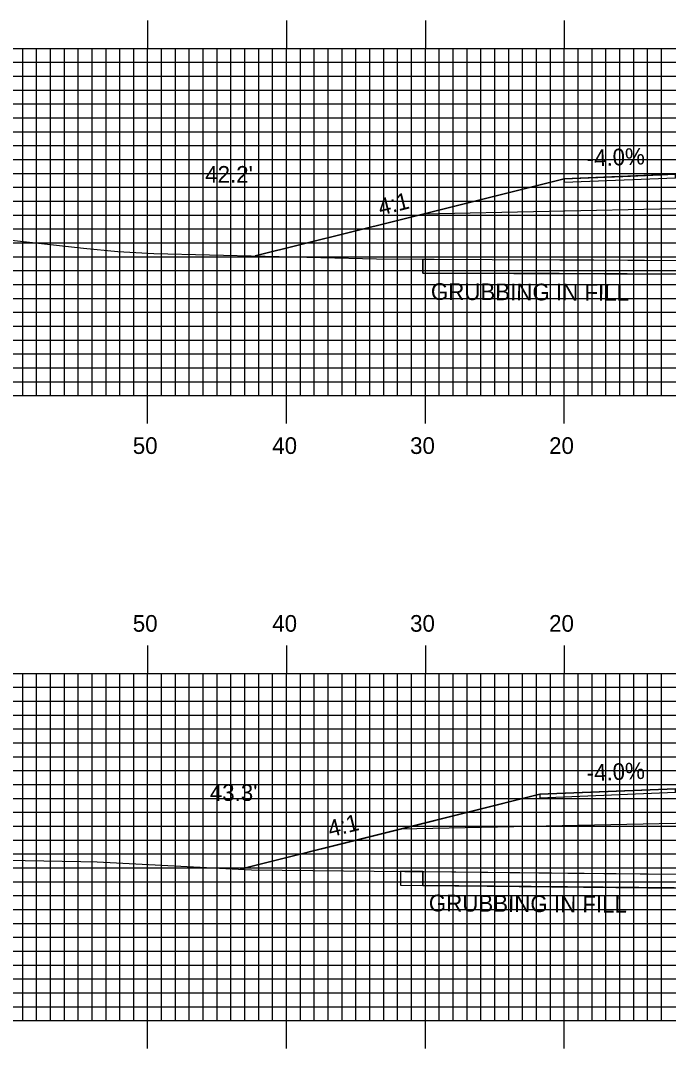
# Model space of a CAD drawing. Extents: x 1773990 to 1774333, y 442591 to 442811.
# Drawn here: x 1774096.5 to 1774143.2, y 442686.7 to 442760.7 of the extents above; entities that cross this region are included whole.
import ezdxf

# ---------------------------------------------------------------- set-up
doc = ezdxf.new("R2010")
doc.units = 0
for name, color, linetype in [('ANNOTATION', 7, 'Continuous'), ('D_Roadway_Centerline', 7, 'Continuous'), ('D_Roadway_Edge_Shoulder', 7, 'Continuous'), ('D_Roadway_SlopeLines', 7, 'Continuous'), ('D_Roadway_SubGrade', 7, 'Continuous'), ('D_Text_Standard', 7, 'Continuous'), ('GRUBBING IN FILL', 7, 'Continuous'), ('H_V ANNOTATION', 7, 'Continuous'), ('MAJOR', 7, 'Continuous'), ('MINOR', 7, 'Continuous'), ('S_Roadway_Centerline', 7, 'Continuous')]:
    doc.layers.add(name, color=color, linetype=linetype)

msp = doc.modelspace()

# ---------------------------------------------------------------- linework, layer by layer
at = {"layer": 'D_Roadway_Centerline'}
for points in [[(1774113.41, 442743.721), (1774123.659, 442746.284), (1774125.485, 442746.74), (1774135.659, 442749.284), (1774139.864, 442749.452), (1774143.659, 442749.604), (1774145.7, 442749.645), (1774155.657, 442749.844), (1774155.659, 442749.844), (1774164.958, 442749.658), (1774167.659, 442749.604), (1774175.659, 442749.284), (1774184.368, 442747.107), (1774185.833, 442746.74), (1774200.249, 442743.136)], [(1774112.312, 442699.568), (1774123.87, 442702.458), (1774133.89, 442704.963), (1774138.828, 442705.161), (1774143.659, 442705.354), (1774143.66, 442705.354), (1774155.659, 442705.594), (1774167.659, 442705.354), (1774171.137, 442705.215), (1774175.659, 442705.034), (1774180.146, 442703.912), (1774185.833, 442702.49), (1774195.567, 442700.056), (1774200.784, 442698.752)]]:
    msp.add_lwpolyline(points, dxfattribs=at)
at = {"layer": 'D_Roadway_Edge_Shoulder'}
for points in [[(1774143.659, 442749.604), (1774135.659, 442749.284), (1774135.659, 442749.034), (1774143.659, 442749.354)], [(1774143.659, 442705.354), (1774133.89, 442704.963), (1774133.89, 442704.713), (1774143.659, 442705.104)]]:
    msp.add_lwpolyline(points, close=True, dxfattribs=at)
at = {"layer": 'D_Roadway_SlopeLines'}
for points in [[(1774135.659, 442749.284), (1774125.485, 442746.74), (1774123.659, 442746.284), (1774113.41, 442743.721)], [(1774133.89, 442704.963), (1774123.716, 442702.419), (1774121.89, 442701.963), (1774112.312, 442699.568)]]:
    msp.add_lwpolyline(points, dxfattribs=at)
at = {"layer": 'D_Roadway_SubGrade'}
for points in [[(1774143.659, 442747.104), (1774125.485, 442746.74), (1774135.659, 442749.284), (1774135.659, 442749.034), (1774143.659, 442749.354), (1774155.659, 442749.594), (1774167.659, 442749.354), (1774175.659, 442749.034), (1774175.659, 442749.284), (1774185.833, 442746.74), (1774167.659, 442747.104), (1774155.659, 442747.344)], [(1774143.659, 442702.854), (1774123.87, 442702.458), (1774133.89, 442704.963), (1774133.89, 442704.713), (1774143.659, 442705.104), (1774155.659, 442705.344), (1774167.659, 442705.104), (1774175.659, 442704.784), (1774175.659, 442705.034), (1774185.833, 442702.49), (1774167.659, 442702.854), (1774155.659, 442703.094)]]:
    msp.add_lwpolyline(points, close=True, dxfattribs=at)
at = {"layer": 'GRUBBING IN FILL'}
for p, q in [((1774125.485, 442743.49), (1774125.485, 442742.49)), ((1774125.485, 442743.49), (1774125.485, 442742.49)), ((1774125.485, 442699.396), (1774124.306, 442699.408)), ((1774125.485, 442699.396), (1774125.485, 442698.396)), ((1774125.485, 442698.396), (1774125.485, 442699.396))]:
    msp.add_line(p, q, dxfattribs=at)
for points in [[(1774125.485, 442743.49), (1774130.474, 442743.468), (1774137.786, 442743.435), (1774145.098, 442743.402), (1774149.402, 442743.416), (1774155.659, 442743.456), (1774155.659, 442742.456), (1774153.713, 442742.43), (1774145.097, 442742.402), (1774135.291, 442742.446), (1774125.485, 442742.49)], [(1774125.485, 442743.49), (1774130.474, 442743.468), (1774137.786, 442743.435), (1774145.098, 442743.402), (1774149.402, 442743.416), (1774155.659, 442743.456), (1774155.659, 442742.456), (1774153.713, 442742.43), (1774145.097, 442742.402), (1774135.291, 442742.446), (1774125.485, 442742.49)], [(1774125.485, 442699.396), (1774135.923, 442699.291), (1774146.312, 442699.187), (1774148.708, 442699.175), (1774154.465, 442699.129), (1774155.659, 442699.119), (1774155.659, 442698.119), (1774154.463, 442698.129), (1774148.7, 442698.175), (1774135.896, 442698.291), (1774125.485, 442698.396)]]:
    msp.add_lwpolyline(points, close=True, dxfattribs=at)
for points in [[(1774125.485, 442742.49), (1774145.097, 442742.402), (1774153.713, 442742.43), (1774168.444, 442742.624), (1774185.833, 442742.248)], [(1774125.485, 442742.49), (1774145.097, 442742.402), (1774153.713, 442742.43), (1774168.444, 442742.624), (1774185.833, 442742.248)], [(1774123.87, 442699.414), (1774123.87, 442698.414), (1774125.485, 442698.396)], [(1774124.306, 442699.408), (1774124.173, 442699.411), (1774123.87, 442699.414)], [(1774123.87, 442699.414), (1774123.87, 442698.414), (1774125.485, 442698.396)], [(1774125.485, 442699.396), (1774135.923, 442699.291), (1774146.312, 442699.187), (1774148.708, 442699.175), (1774154.465, 442699.129), (1774155.659, 442699.119), (1774155.659, 442698.119), (1774154.463, 442698.129), (1774148.7, 442698.175), (1774135.896, 442698.291), (1774125.485, 442698.396)], [(1774125.485, 442698.396), (1774146.307, 442698.187), (1774147.443, 442698.186), (1774148.7, 442698.175), (1774160.225, 442698.083), (1774169.375, 442698.218), (1774170.955, 442698.257), (1774172.934, 442698.185), (1774182.967, 442698.114), (1774185.833, 442698.019)], [(1774125.485, 442698.396), (1774146.307, 442698.187), (1774147.443, 442698.186), (1774148.7, 442698.175), (1774160.225, 442698.083), (1774169.375, 442698.218), (1774170.955, 442698.257), (1774172.934, 442698.185), (1774182.967, 442698.114), (1774185.833, 442698.019)]]:
    msp.add_lwpolyline(points, dxfattribs=at)
at = {"layer": 'MAJOR'}
for p, q in [((1774105.659, 442760.669), (1774105.659, 442758.665)), ((1774115.659, 442760.669), (1774115.659, 442758.665)), ((1774125.659, 442760.669), (1774125.659, 442758.665)), ((1774135.659, 442760.669), (1774135.659, 442758.665)), ((1774015.659, 442758.665), (1774295.659, 442758.665)), ((1774015.659, 442758.665), (1774295.659, 442758.665)), ((1774105.659, 442733.665), (1774105.659, 442758.665)), ((1774115.659, 442733.665), (1774115.659, 442758.665)), ((1774125.659, 442733.665), (1774125.659, 442758.665)), ((1774135.659, 442733.665), (1774135.659, 442758.665)), ((1774015.659, 442753.665), (1774295.659, 442753.665)), ((1774015.659, 442748.665), (1774295.659, 442748.665)), ((1774015.659, 442743.665), (1774295.659, 442743.665)), ((1774015.659, 442738.665), (1774295.659, 442738.665)), ((1774015.659, 442733.665), (1774295.659, 442733.665)), ((1774015.659, 442733.665), (1774295.659, 442733.665)), ((1774105.659, 442731.661), (1774105.659, 442733.665)), ((1774115.659, 442731.661), (1774115.659, 442733.665)), ((1774125.659, 442731.661), (1774125.659, 442733.665)), ((1774135.659, 442731.661), (1774135.659, 442733.665)), ((1774105.659, 442715.669), (1774105.659, 442713.665)), ((1774115.659, 442715.669), (1774115.659, 442713.665)), ((1774125.659, 442715.669), (1774125.659, 442713.665)), ((1774135.659, 442715.669), (1774135.659, 442713.665)), ((1774015.659, 442713.665), (1774295.659, 442713.665)), ((1774015.659, 442713.665), (1774295.659, 442713.665)), ((1774105.659, 442688.665), (1774105.659, 442713.665)), ((1774115.659, 442688.665), (1774115.659, 442713.665)), ((1774125.659, 442688.665), (1774125.659, 442713.665)), ((1774135.659, 442688.665), (1774135.659, 442713.665)), ((1774015.659, 442708.665), (1774295.659, 442708.665)), ((1774015.659, 442703.665), (1774295.659, 442703.665)), ((1774015.659, 442698.665), (1774295.659, 442698.665)), ((1774015.659, 442693.665), (1774295.659, 442693.665)), ((1774015.659, 442688.665), (1774295.659, 442688.665)), ((1774015.659, 442688.665), (1774295.659, 442688.665)), ((1774105.659, 442686.661), (1774105.659, 442688.665)), ((1774115.659, 442686.661), (1774115.659, 442688.665)), ((1774125.659, 442686.661), (1774125.659, 442688.665)), ((1774135.659, 442686.661), (1774135.659, 442688.665))]:
    msp.add_line(p, q, dxfattribs=at)
at = {"layer": 'MINOR'}
for p, q in [((1774096.659, 442733.665), (1774096.659, 442758.665)), ((1774097.659, 442733.665), (1774097.659, 442758.665)), ((1774098.659, 442733.665), (1774098.659, 442758.665)), ((1774099.659, 442733.665), (1774099.659, 442758.665)), ((1774100.659, 442733.665), (1774100.659, 442758.665)), ((1774101.659, 442733.665), (1774101.659, 442758.665)), ((1774102.659, 442733.665), (1774102.659, 442758.665)), ((1774103.659, 442733.665), (1774103.659, 442758.665)), ((1774104.659, 442733.665), (1774104.659, 442758.665)), ((1774106.659, 442733.665), (1774106.659, 442758.665)), ((1774107.659, 442733.665), (1774107.659, 442758.665)), ((1774108.659, 442733.665), (1774108.659, 442758.665)), ((1774109.659, 442733.665), (1774109.659, 442758.665)), ((1774110.659, 442733.665), (1774110.659, 442758.665)), ((1774111.659, 442733.665), (1774111.659, 442758.665)), ((1774112.659, 442733.665), (1774112.659, 442758.665)), ((1774113.659, 442733.665), (1774113.659, 442758.665)), ((1774114.659, 442733.665), (1774114.659, 442758.665)), ((1774116.659, 442733.665), (1774116.659, 442758.665)), ((1774117.659, 442733.665), (1774117.659, 442758.665)), ((1774118.659, 442733.665), (1774118.659, 442758.665)), ((1774119.659, 442733.665), (1774119.659, 442758.665)), ((1774120.659, 442733.665), (1774120.659, 442758.665)), ((1774121.659, 442733.665), (1774121.659, 442758.665)), ((1774122.659, 442733.665), (1774122.659, 442758.665)), ((1774123.659, 442733.665), (1774123.659, 442758.665)), ((1774124.659, 442733.665), (1774124.659, 442758.665)), ((1774126.659, 442733.665), (1774126.659, 442758.665)), ((1774127.659, 442733.665), (1774127.659, 442758.665)), ((1774128.659, 442733.665), (1774128.659, 442758.665)), ((1774129.659, 442733.665), (1774129.659, 442758.665)), ((1774130.659, 442733.665), (1774130.659, 442758.665)), ((1774131.659, 442733.665), (1774131.659, 442758.665)), ((1774132.659, 442733.665), (1774132.659, 442758.665)), ((1774133.659, 442733.665), (1774133.659, 442758.665)), ((1774134.659, 442733.665), (1774134.659, 442758.665)), ((1774136.659, 442733.665), (1774136.659, 442758.665)), ((1774137.659, 442733.665), (1774137.659, 442758.665)), ((1774138.659, 442733.665), (1774138.659, 442758.665)), ((1774139.659, 442733.665), (1774139.659, 442758.665)), ((1774140.659, 442733.665), (1774140.659, 442758.665)), ((1774141.659, 442733.665), (1774141.659, 442758.665)), ((1774142.659, 442733.665), (1774142.659, 442758.665)), ((1774015.659, 442757.665), (1774295.659, 442757.665)), ((1774015.659, 442756.665), (1774295.659, 442756.665)), ((1774015.659, 442755.665), (1774295.659, 442755.665)), ((1774015.659, 442754.665), (1774295.659, 442754.665)), ((1774015.659, 442752.665), (1774295.659, 442752.665)), ((1774015.659, 442751.665), (1774295.659, 442751.665)), ((1774015.659, 442750.665), (1774295.659, 442750.665)), ((1774015.659, 442749.665), (1774295.659, 442749.665)), ((1774015.659, 442747.665), (1774295.659, 442747.665)), ((1774015.659, 442746.665), (1774295.659, 442746.665)), ((1774015.659, 442745.665), (1774295.659, 442745.665)), ((1774015.659, 442744.665), (1774295.659, 442744.665)), ((1774015.659, 442742.665), (1774295.659, 442742.665)), ((1774015.659, 442741.665), (1774295.659, 442741.665)), ((1774015.659, 442740.665), (1774295.659, 442740.665)), ((1774015.659, 442739.665), (1774295.659, 442739.665)), ((1774015.659, 442737.665), (1774295.659, 442737.665)), ((1774015.659, 442736.665), (1774295.659, 442736.665)), ((1774015.659, 442735.665), (1774295.659, 442735.665)), ((1774015.659, 442734.665), (1774295.659, 442734.665)), ((1774096.659, 442688.665), (1774096.659, 442713.665)), ((1774097.659, 442688.665), (1774097.659, 442713.665)), ((1774098.659, 442688.665), (1774098.659, 442713.665)), ((1774099.659, 442688.665), (1774099.659, 442713.665)), ((1774100.659, 442688.665), (1774100.659, 442713.665)), ((1774101.659, 442688.665), (1774101.659, 442713.665)), ((1774102.659, 442688.665), (1774102.659, 442713.665)), ((1774103.659, 442688.665), (1774103.659, 442713.665)), ((1774104.659, 442688.665), (1774104.659, 442713.665)), ((1774106.659, 442688.665), (1774106.659, 442713.665)), ((1774107.659, 442688.665), (1774107.659, 442713.665)), ((1774108.659, 442688.665), (1774108.659, 442713.665)), ((1774109.659, 442688.665), (1774109.659, 442713.665)), ((1774110.659, 442688.665), (1774110.659, 442713.665)), ((1774111.659, 442688.665), (1774111.659, 442713.665)), ((1774112.659, 442688.665), (1774112.659, 442713.665)), ((1774113.659, 442688.665), (1774113.659, 442713.665)), ((1774114.659, 442688.665), (1774114.659, 442713.665)), ((1774116.659, 442688.665), (1774116.659, 442713.665)), ((1774117.659, 442688.665), (1774117.659, 442713.665)), ((1774118.659, 442688.665), (1774118.659, 442713.665)), ((1774119.659, 442688.665), (1774119.659, 442713.665)), ((1774120.659, 442688.665), (1774120.659, 442713.665)), ((1774121.659, 442688.665), (1774121.659, 442713.665)), ((1774122.659, 442688.665), (1774122.659, 442713.665)), ((1774123.659, 442688.665), (1774123.659, 442713.665)), ((1774124.659, 442688.665), (1774124.659, 442713.665)), ((1774126.659, 442688.665), (1774126.659, 442713.665)), ((1774127.659, 442688.665), (1774127.659, 442713.665)), ((1774128.659, 442688.665), (1774128.659, 442713.665)), ((1774129.659, 442688.665), (1774129.659, 442713.665)), ((1774130.659, 442688.665), (1774130.659, 442713.665)), ((1774131.659, 442688.665), (1774131.659, 442713.665)), ((1774132.659, 442688.665), (1774132.659, 442713.665)), ((1774133.659, 442688.665), (1774133.659, 442713.665)), ((1774134.659, 442688.665), (1774134.659, 442713.665)), ((1774136.659, 442688.665), (1774136.659, 442713.665)), ((1774137.659, 442688.665), (1774137.659, 442713.665)), ((1774138.659, 442688.665), (1774138.659, 442713.665)), ((1774139.659, 442688.665), (1774139.659, 442713.665)), ((1774140.659, 442688.665), (1774140.659, 442713.665)), ((1774141.659, 442688.665), (1774141.659, 442713.665)), ((1774142.659, 442688.665), (1774142.659, 442713.665)), ((1774015.659, 442712.665), (1774295.659, 442712.665)), ((1774015.659, 442711.665), (1774295.659, 442711.665)), ((1774015.659, 442710.665), (1774295.659, 442710.665)), ((1774015.659, 442709.665), (1774295.659, 442709.665)), ((1774015.659, 442707.665), (1774295.659, 442707.665)), ((1774015.659, 442706.665), (1774295.659, 442706.665)), ((1774015.659, 442705.665), (1774295.659, 442705.665)), ((1774015.659, 442704.665), (1774295.659, 442704.665)), ((1774015.659, 442702.665), (1774295.659, 442702.665)), ((1774015.659, 442701.665), (1774295.659, 442701.665)), ((1774015.659, 442700.665), (1774295.659, 442700.665)), ((1774015.659, 442699.665), (1774295.659, 442699.665)), ((1774015.659, 442697.665), (1774295.659, 442697.665)), ((1774015.659, 442696.665), (1774295.659, 442696.665)), ((1774015.659, 442695.665), (1774295.659, 442695.665)), ((1774015.659, 442694.665), (1774295.659, 442694.665)), ((1774015.659, 442692.665), (1774295.659, 442692.665)), ((1774015.659, 442691.665), (1774295.659, 442691.665)), ((1774015.659, 442690.665), (1774295.659, 442690.665)), ((1774015.659, 442689.665), (1774295.659, 442689.665))]:
    msp.add_line(p, q, dxfattribs=at)
at = {"layer": 'S_Roadway_Centerline'}
for points in [[(1774015.659, 442746.914), (1774021.875, 442746.854), (1774032.904, 442746.671), (1774034.207, 442746.662), (1774035.508, 442746.663), (1774045.562, 442746.752), (1774054.116, 442746.226), (1774059.287, 442746.02), (1774078.992, 442745.503), (1774080.613, 442745.485), (1774082.548, 442745.428), (1774091.734, 442745.312), (1774101.032, 442744.283), (1774103.519, 442744.031), (1774106.112, 442743.902), (1774122.137, 442743.506), (1774130.474, 442743.468), (1774145.098, 442743.402), (1774153.705, 442743.43), (1774168.448, 442743.624), (1774177.508, 442743.428), (1774190.118, 442743.156), (1774200.849, 442743.135), (1774211.65, 442743.192)], [(1774090.142, 442700.311), (1774100.842, 442700.131), (1774102.018, 442700.106), (1774113.135, 442699.525), (1774124.173, 442699.411), (1774124.306, 442699.408), (1774125.534, 442699.396), (1774146.312, 442699.187), (1774147.448, 442699.186), (1774148.708, 442699.175), (1774160.222, 442699.083), (1774169.356, 442699.218), (1774170.96, 442699.257), (1774172.955, 442699.185), (1774182.987, 442699.114), (1774191.809, 442698.821), (1774195.172, 442698.825), (1774197.059, 442698.815), (1774217.324, 442698.473)]]:
    msp.add_lwpolyline(points, dxfattribs=at)

# ---------------------------------------------------------------- texts
at = {"layer": 'ANNOTATION'}
for s, rotation, p in [('-4.0%', 2.29053, (1774137.291, 442750.151)), ('4:1', 14.0396, (1774122.422, 442746.619)), ('-4.0%', 2.29056, (1774137.291, 442705.901)), ('4:1', 14.03928, (1774118.805, 442701.859))]:
    msp.add_text(s, height=1.2, rotation=rotation, dxfattribs=at).set_placement(p)
at = {"layer": 'D_Text_Standard'}
for s, p in [("42.2'", (1774109.804, 442748.994)), ("43.3'", (1774110.135, 442704.483))]:
    msp.add_text(s, height=1.2, dxfattribs=at).set_placement(p)
at = {"layer": 'GRUBBING IN FILL'}
for rotation, p in [(359.74859, (1774126.051, 442740.558)), (359.6085, (1774125.901, 442696.534))]:
    msp.add_text('GRUBBING IN FILL', height=1.2, rotation=rotation, dxfattribs=at).set_placement(p)
at = {"layer": 'H_V ANNOTATION'}
for s, p in [('50', (1774104.588, 442729.465)), ('40', (1774114.631, 442729.465)), ('30', (1774124.556, 442729.465)), ('20', (1774134.567, 442729.465)), ('50', (1774104.588, 442716.665)), ('40', (1774114.631, 442716.665)), ('30', (1774124.556, 442716.665)), ('20', (1774134.567, 442716.665))]:
    msp.add_text(s, height=1.2, dxfattribs=at).set_placement(p)

doc.saveas('drawing.dxf')
